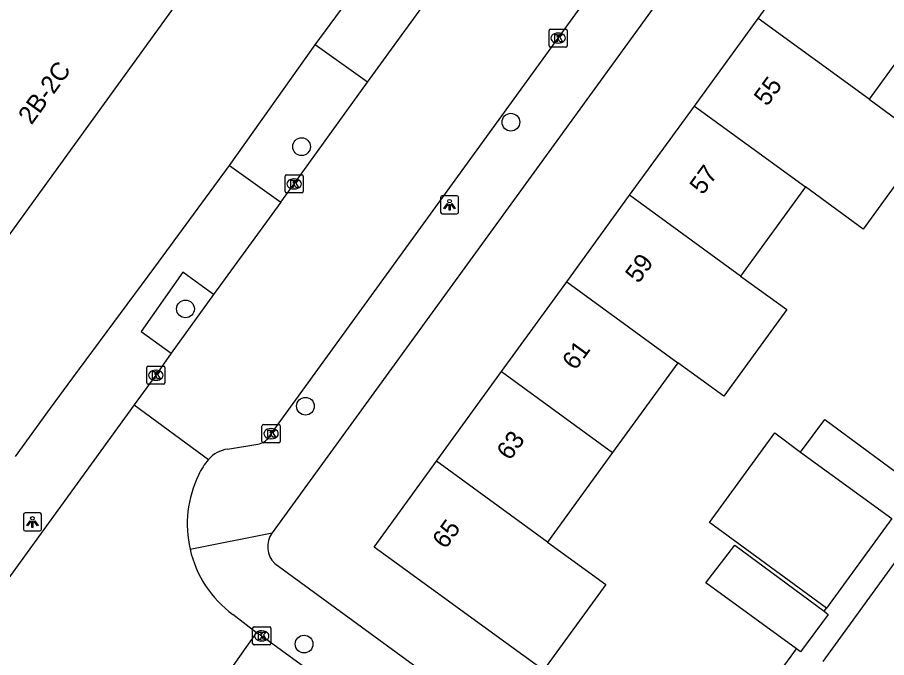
# Model space of a CAD drawing. Extents: x 159675 to 160530, y 382179 to 382901.
# Drawn here: x 160052.54 to 160100.56, y 382525.17 to 382560.51 of the extents above; entities that cross this region are included whole.
import ezdxf

# ---------------------------------------------------------------- set-up
doc = ezdxf.new("R2010")
doc.units = 0
for name, color, linetype in [('IMGEO_Boom', 7, 'Continuous'), ('IMGEO_Kolk', 7, 'Continuous'), ('IMGEO_Lichtpunt', 7, 'Continuous'), ('IMGEO_Pand', 7, 'Continuous'), ('IMGEO_Pand_nummerreeks', 7, 'Continuous'), ('IMGEO_Rijbaan_lokaal_open', 7, 'Continuous'), ('IMGEO_Voetpad_open', 7, 'Continuous')]:
    doc.layers.add(name, color=color, linetype=linetype)

msp = doc.modelspace()

# ---------------------------------------------------------------- linework, layer by layer
at = {"layer": 'IMGEO_Boom'}
for centre in [(160079.803, 382554.724), (160068.243, 382553.373), (160061.83, 382544.417), (160068.457, 382539.049), (160068.381, 382525.919)]:
    msp.add_circle(centre, 0.489, dxfattribs=at)
at = {"layer": 'IMGEO_Kolk'}
for p, q in [((160081.91, 382558.94), (160081.91, 382559.792)), ((160081.985, 382559.866), (160082.837, 382559.866)), ((160082.911, 382559.792), (160082.911, 382558.94)), ((160082.398, 382559.646), (160082.423, 382559.646)), ((160082.837, 382558.866), (160081.985, 382558.866)), ((160082.421, 382559.086), (160082.396, 382559.086)), ((160067.328, 382550.891), (160067.328, 382551.743)), ((160067.403, 382551.817), (160068.255, 382551.817)), ((160067.816, 382551.597), (160067.841, 382551.597)), ((160068.329, 382551.743), (160068.329, 382550.891)), ((160068.255, 382550.817), (160067.403, 382550.817)), ((160067.839, 382551.037), (160067.814, 382551.037)), ((160059.691, 382540.331), (160059.691, 382541.183)), ((160059.766, 382541.257), (160060.618, 382541.257)), ((160060.179, 382541.037), (160060.204, 382541.037)), ((160060.692, 382541.183), (160060.692, 382540.331)), ((160060.618, 382540.257), (160059.766, 382540.257)), ((160060.202, 382540.477), (160060.177, 382540.477)), ((160066.056, 382537.106), (160066.056, 382537.958)), ((160066.131, 382538.032), (160066.983, 382538.032)), ((160066.544, 382537.812), (160066.569, 382537.812)), ((160067.057, 382537.958), (160067.057, 382537.106)), ((160066.567, 382537.252), (160066.542, 382537.252)), ((160066.983, 382537.032), (160066.131, 382537.032)), ((160065.54, 382525.947), (160065.54, 382526.799)), ((160065.615, 382526.873), (160066.467, 382526.873)), ((160066.028, 382526.653), (160066.053, 382526.653)), ((160066.541, 382526.799), (160066.541, 382525.947)), ((160066.467, 382525.873), (160065.615, 382525.873)), ((160066.051, 382526.093), (160066.026, 382526.093))]:
    msp.add_line(p, q, dxfattribs=at)
for points in [[(160081.91, 382558.94), (160081.91, 382559.792)], [(160081.985, 382559.866), (160082.837, 382559.866)], [(160082.911, 382559.792), (160082.911, 382558.94)], [(160082.231, 382559.566), (160082.354, 382559.566), (160082.354, 382559.415), (160082.484, 382559.566), (160082.648, 382559.566), (160082.502, 382559.415), (160082.655, 382559.166), (160082.503, 382559.166), (160082.418, 382559.33), (160082.354, 382559.263), (160082.354, 382559.166), (160082.231, 382559.166), (160082.231, 382559.566)], [(160082.837, 382558.866), (160081.985, 382558.866)], [(160067.328, 382550.891), (160067.328, 382551.743)], [(160067.403, 382551.817), (160068.255, 382551.817)], [(160068.329, 382551.743), (160068.329, 382550.891)], [(160067.649, 382551.517), (160067.772, 382551.517), (160067.772, 382551.366), (160067.902, 382551.517), (160068.066, 382551.517), (160067.92, 382551.366), (160068.073, 382551.117), (160067.921, 382551.117), (160067.836, 382551.281), (160067.772, 382551.214), (160067.772, 382551.117), (160067.649, 382551.117), (160067.649, 382551.517)], [(160068.255, 382550.817), (160067.403, 382550.817)], [(160059.691, 382540.331), (160059.691, 382541.183)], [(160059.766, 382541.257), (160060.618, 382541.257)], [(160060.692, 382541.183), (160060.692, 382540.331)], [(160060.012, 382540.957), (160060.135, 382540.957), (160060.135, 382540.806), (160060.265, 382540.957), (160060.429, 382540.957), (160060.283, 382540.806), (160060.436, 382540.557), (160060.284, 382540.557), (160060.199, 382540.721), (160060.135, 382540.654), (160060.135, 382540.557), (160060.012, 382540.557), (160060.012, 382540.957)], [(160060.618, 382540.257), (160059.766, 382540.257)], [(160066.056, 382537.106), (160066.056, 382537.958)], [(160066.131, 382538.032), (160066.983, 382538.032)], [(160066.377, 382537.732), (160066.5, 382537.732), (160066.5, 382537.581), (160066.63, 382537.732), (160066.794, 382537.732), (160066.648, 382537.581), (160066.801, 382537.332), (160066.649, 382537.332), (160066.564, 382537.496), (160066.5, 382537.429), (160066.5, 382537.332), (160066.377, 382537.332), (160066.377, 382537.732)], [(160067.057, 382537.958), (160067.057, 382537.106)], [(160066.983, 382537.032), (160066.131, 382537.032)], [(160065.54, 382525.947), (160065.54, 382526.799)], [(160065.615, 382526.873), (160066.467, 382526.873)], [(160066.541, 382526.799), (160066.541, 382525.947)], [(160065.861, 382526.573), (160065.984, 382526.573), (160065.984, 382526.422), (160066.114, 382526.573), (160066.278, 382526.573), (160066.132, 382526.422), (160066.285, 382526.173), (160066.133, 382526.173), (160066.048, 382526.337), (160065.984, 382526.27), (160065.984, 382526.173), (160065.861, 382526.173), (160065.861, 382526.573)], [(160066.467, 382525.873), (160065.615, 382525.873)]]:
    msp.add_lwpolyline(points, dxfattribs=at)
for centre, start, end in [((160081.987, 382559.79), 91.552, 178.448), ((160081.987, 382559.79), 91.552, 178.448), ((160082.835, 382559.79), 1.552, 88.448), ((160082.835, 382559.79), 1.552, 88.448), ((160081.987, 382558.942), 181.552, 268.448), ((160081.987, 382558.942), 181.552, 268.448), ((160082.835, 382558.942), 271.552, 358.448), ((160082.835, 382558.942), 271.552, 358.448), ((160067.405, 382551.741), 91.552, 178.448), ((160067.405, 382551.741), 91.552, 178.448), ((160068.253, 382551.741), 1.552, 88.448), ((160068.253, 382551.741), 1.552, 88.448), ((160067.405, 382550.893), 181.552, 268.448), ((160067.405, 382550.893), 181.552, 268.448), ((160068.253, 382550.893), 271.552, 358.448), ((160068.253, 382550.893), 271.552, 358.448), ((160059.768, 382541.181), 91.552, 178.448), ((160059.768, 382541.181), 91.552, 178.448), ((160060.616, 382541.181), 1.552, 88.448), ((160060.616, 382541.181), 1.552, 88.448), ((160059.768, 382540.333), 181.552, 268.448), ((160059.768, 382540.333), 181.552, 268.448), ((160060.616, 382540.333), 271.552, 358.448), ((160060.616, 382540.333), 271.552, 358.448), ((160066.133, 382537.956), 91.552, 178.448), ((160066.133, 382537.956), 91.552, 178.448), ((160066.981, 382537.956), 1.552, 88.448), ((160066.981, 382537.956), 1.552, 88.448), ((160066.133, 382537.108), 181.552, 268.448), ((160066.133, 382537.108), 181.552, 268.448), ((160066.981, 382537.108), 271.552, 358.448), ((160066.981, 382537.108), 271.552, 358.448), ((160065.617, 382526.797), 91.552, 178.448), ((160065.617, 382526.797), 91.552, 178.448), ((160066.465, 382526.797), 1.552, 88.448), ((160066.465, 382526.797), 1.552, 88.448), ((160065.617, 382525.949), 181.552, 268.448), ((160065.617, 382525.949), 181.552, 268.448), ((160066.465, 382525.949), 271.552, 358.448), ((160066.465, 382525.949), 271.552, 358.448)]:
    msp.add_arc(centre, 0.0765, start, end, dxfattribs=at)
for centre, major_axis, ratio, start_param, end_param in [((160082.397, 382559.366), (-0.387, 0.002), 0.722429, 4.712389, 7.853982), ((160082.422, 382559.366), (-0.39, 0.002), 0.717154, 1.570796, 4.712389), ((160067.815, 382551.317), (-0.387, 0.002), 0.722429, 4.712389, 7.853982), ((160067.84, 382551.317), (-0.39, 0.002), 0.717154, 1.570796, 4.712389), ((160060.178, 382540.757), (-0.387, 0.002), 0.722429, 4.712389, 7.853982), ((160060.203, 382540.757), (-0.39, 0.002), 0.717154, 1.570796, 4.712389), ((160066.543, 382537.532), (-0.387, 0.002), 0.722429, 4.712389, 7.853982), ((160066.568, 382537.532), (-0.39, 0.002), 0.717154, 1.570796, 4.712389), ((160066.027, 382526.373), (-0.387, 0.002), 0.722429, 4.712389, 7.853982), ((160066.052, 382526.373), (-0.39, 0.002), 0.717154, 1.570796, 4.712389)]:
    msp.add_ellipse(centre, major_axis=major_axis, ratio=ratio, start_param=start_param, end_param=end_param, dxfattribs=at)
at = {"layer": 'IMGEO_Lichtpunt'}
for p, q in [((160076.822, 382550.663), (160076.014, 382550.663)), ((160076.822, 382550.663), (160076.014, 382550.663)), ((160075.92, 382550.568), (160075.92, 382549.761)), ((160075.92, 382550.568), (160075.92, 382549.761)), ((160076.916, 382549.761), (160076.916, 382550.568)), ((160076.916, 382549.761), (160076.916, 382550.568)), ((160076.014, 382549.667), (160076.822, 382549.667)), ((160076.014, 382549.667), (160076.822, 382549.667)), ((160052.876, 382533.066), (160052.876, 382532.259)), ((160052.876, 382533.066), (160052.876, 382532.259)), ((160053.778, 382533.161), (160052.97, 382533.161)), ((160053.778, 382533.161), (160052.97, 382533.161)), ((160053.872, 382532.259), (160053.872, 382533.066)), ((160053.872, 382532.259), (160053.872, 382533.066)), ((160052.97, 382532.165), (160053.778, 382532.165)), ((160052.97, 382532.165), (160053.778, 382532.165))]:
    msp.add_line(p, q, dxfattribs=at)
for points in [[(160076.294, 382550.232), (160076.333, 382550.204), (160076.145, 382549.942), (160076.107, 382549.969), (160076.294, 382550.232)], [(160076.396, 382550.184), (160076.443, 382550.184), (160076.443, 382549.862), (160076.396, 382549.862), (160076.396, 382550.184)], [(160076.506, 382550.204), (160076.544, 382550.231), (160076.731, 382549.969), (160076.692, 382549.941), (160076.506, 382550.204)], [(160053.25, 382532.73), (160053.289, 382532.702), (160053.101, 382532.44), (160053.063, 382532.467), (160053.25, 382532.73)], [(160053.352, 382532.682), (160053.399, 382532.682), (160053.399, 382532.36), (160053.352, 382532.36), (160053.352, 382532.682)], [(160053.462, 382532.702), (160053.5, 382532.729), (160053.687, 382532.467), (160053.648, 382532.439), (160053.462, 382532.702)]]:
    msp.add_lwpolyline(points, dxfattribs=at)
for centre in [(160076.419, 382550.366), (160053.375, 382532.864)]:
    msp.add_circle(centre, 0.0994, dxfattribs=at)
for centre, start, end in [((160076.014, 382550.568), 90, 180), ((160076.014, 382550.568), 90, 180), ((160076.822, 382550.568), 0, 90), ((160076.822, 382550.568), 0, 90), ((160076.014, 382549.761), 180, 270), ((160076.014, 382549.761), 180, 270), ((160076.822, 382549.761), 270, 0), ((160076.822, 382549.761), 270, 360), ((160052.97, 382533.066), 90, 180), ((160052.97, 382533.066), 90, 180), ((160053.778, 382533.066), 0, 90), ((160053.778, 382533.066), 0, 90), ((160052.97, 382532.259), 180, 270), ((160052.97, 382532.259), 180, 270), ((160053.778, 382532.259), 270, 0), ((160053.778, 382532.259), 270, 360)]:
    msp.add_arc(centre, 0.0946, start, end, dxfattribs=at)
at = {"layer": 'IMGEO_Pand'}
for points in [[(160068.999, 382576.024), (160073.063, 382573.111), (160069.597, 382568.294), (160069.324, 382568.488), (160068.201, 382566.953), (160068.292, 382566.873), (160066.759, 382564.747), (160066.664, 382564.815), (160064.516, 382561.824), (160062.689, 382563.177), (160051.094, 382547.163)], [(160093.458, 382560.448), (160097.119, 382565.484), (160103.251, 382561.027), (160099.59, 382555.99)], [(160089.94, 382555.608), (160093.458, 382560.448)], [(160099.59, 382555.99), (160093.458, 382560.448)], [(160099.59, 382555.99), (160102.783, 382553.66), (160099.269, 382548.826), (160096.071, 382551.151)], [(160086.364, 382550.69), (160089.94, 382555.608)], [(160089.94, 382555.608), (160096.071, 382551.151)], [(160096.071, 382551.151), (160092.496, 382546.232)], [(160082.886, 382545.905), (160086.364, 382550.69)], [(160092.496, 382546.232), (160086.364, 382550.69)], [(160079.288, 382540.956), (160082.886, 382545.905)], [(160082.886, 382545.905), (160089.018, 382541.448)], [(160092.496, 382546.232), (160095.042, 382544.381), (160091.565, 382539.597), (160089.018, 382541.448)], [(160089.018, 382541.448), (160085.42, 382536.499)], [(160075.691, 382536.008), (160079.288, 382540.956)], [(160079.288, 382540.956), (160085.42, 382536.499)], [(160095.808, 382536.513), (160097.141, 382538.309), (160102.285, 382534.528)], [(160097.235, 382527.911), (160090.777, 382532.632), (160094.387, 382537.572), (160095.808, 382536.513)], [(160085.42, 382536.499), (160081.824, 382531.551)], [(160095.808, 382536.513), (160100.846, 382532.851)], [(160081.824, 382531.551), (160085.04, 382529.214), (160081.597, 382524.477), (160078.381, 382526.815), (160072.249, 382531.273), (160075.691, 382536.008)], [(160081.824, 382531.551), (160075.691, 382536.008)], [(160100.846, 382532.851), (160097.235, 382527.911)], [(160095.576, 382525.656), (160090.568, 382529.296), (160092.172, 382531.385), (160097.103, 382527.733)], [(160097.103, 382527.733), (160097.338, 382527.559), (160095.8, 382525.493), (160095.576, 382525.656)]]:
    msp.add_lwpolyline(points, dxfattribs=at)
at = {"layer": 'IMGEO_Rijbaan_lokaal_open'}
for points in [[(160066.449, 382537.355), (160066.557, 382537.532), (160082.411, 382559.366), (160090.741, 382570.837)], [(160071.89, 382556.928), (160076.064, 382562.694)], [(160067.089, 382550.301), (160067.829, 382551.317), (160071.89, 382556.928)], [(160067.089, 382550.301), (160063.381, 382545.206)], [(160063.381, 382545.206), (160061.047, 382541.977)], [(160061.047, 382541.977), (160060.192, 382540.757), (160059.002, 382539.131)], [(160059.002, 382539.131), (160047.551, 382523.358)], [(160059.002, 382539.131), (160063.104, 382536.111)], [(160064.148, 382536.686), (160065.82, 382536.96)], [(160065.761, 382526.548), (160064.445, 382527.55)], [(160061.728, 382520.822), (160065.761, 382526.548)], [(160065.761, 382526.548), (160066.041, 382526.373), (160086.083, 382511.782), (160148.312, 382466.705), (160171.029, 382450.249)]]:
    msp.add_lwpolyline(points, dxfattribs=at)
for centre, radius, start, end in [((160065.729, 382537.803), 0.848, 276.1682, 328.0879), ((160064.422, 382534.954), 1.754, 98.9789, 138.7101), ((160065.777, 382533.796), 3.536, 139.1001, 155.6992), ((160068.118, 382532.535), 6.191, 153.9807, 192.9095), ((160068.122, 382532.537), 6.196, 192.914, 233.5954)]:
    msp.add_arc(centre, radius, start, end, dxfattribs=at)
at = {"layer": 'IMGEO_Voetpad_open'}
for points in [[(160094.261, 382570.107), (160066.611, 382532.056)], [(160068.989, 382558.995), (160073.24, 382564.766)], [(160064.26, 382552.334), (160068.989, 382558.995)], [(160071.89, 382556.928), (160068.989, 382558.995)], [(160052.445, 382536.281), (160054.378, 382538.936), (160055.599, 382540.613), (160060.131, 382546.714), (160064.26, 382552.334)], [(160064.26, 382552.334), (160067.089, 382550.301)], [(160063.381, 382545.206), (160061.676, 382546.441), (160059.381, 382543.178), (160061.047, 382541.977)], [(160103.961, 382534.26), (160103.851, 382534.341), (160097.038, 382524.967)], [(160062.083, 382531.152), (160066.611, 382532.056)], [(160066.763, 382530.365), (160087.821, 382514.988)], [(160097.103, 382527.733), (160097.235, 382527.911)], [(160093.702, 382523.077), (160095.576, 382525.656)]]:
    msp.add_lwpolyline(points, dxfattribs=at)
msp.add_arc((160067.66, 382531.298), 1.294, 144.1496, 226.1232, dxfattribs=at)

# ---------------------------------------------------------------- texts
at = {"layer": 'IMGEO_Pand_nummerreeks'}
for s, rotation, p in [('2B-2C', 54.0934, (160053.322, 382554.536)), ('55', 53.9841, (160093.956, 382555.556)), ('57', 53.9844, (160090.405, 382550.669)), ('59', 53.9841, (160086.851, 382545.781)), ('61', 53.9844, (160083.365, 382540.985)), ('63', 53.9844, (160079.746, 382536.007)), ('65', 53.9841, (160076.192, 382531.119))]:
    msp.add_text(s, height=1, rotation=rotation, dxfattribs=at).set_placement(p)

doc.saveas('drawing.dxf')
